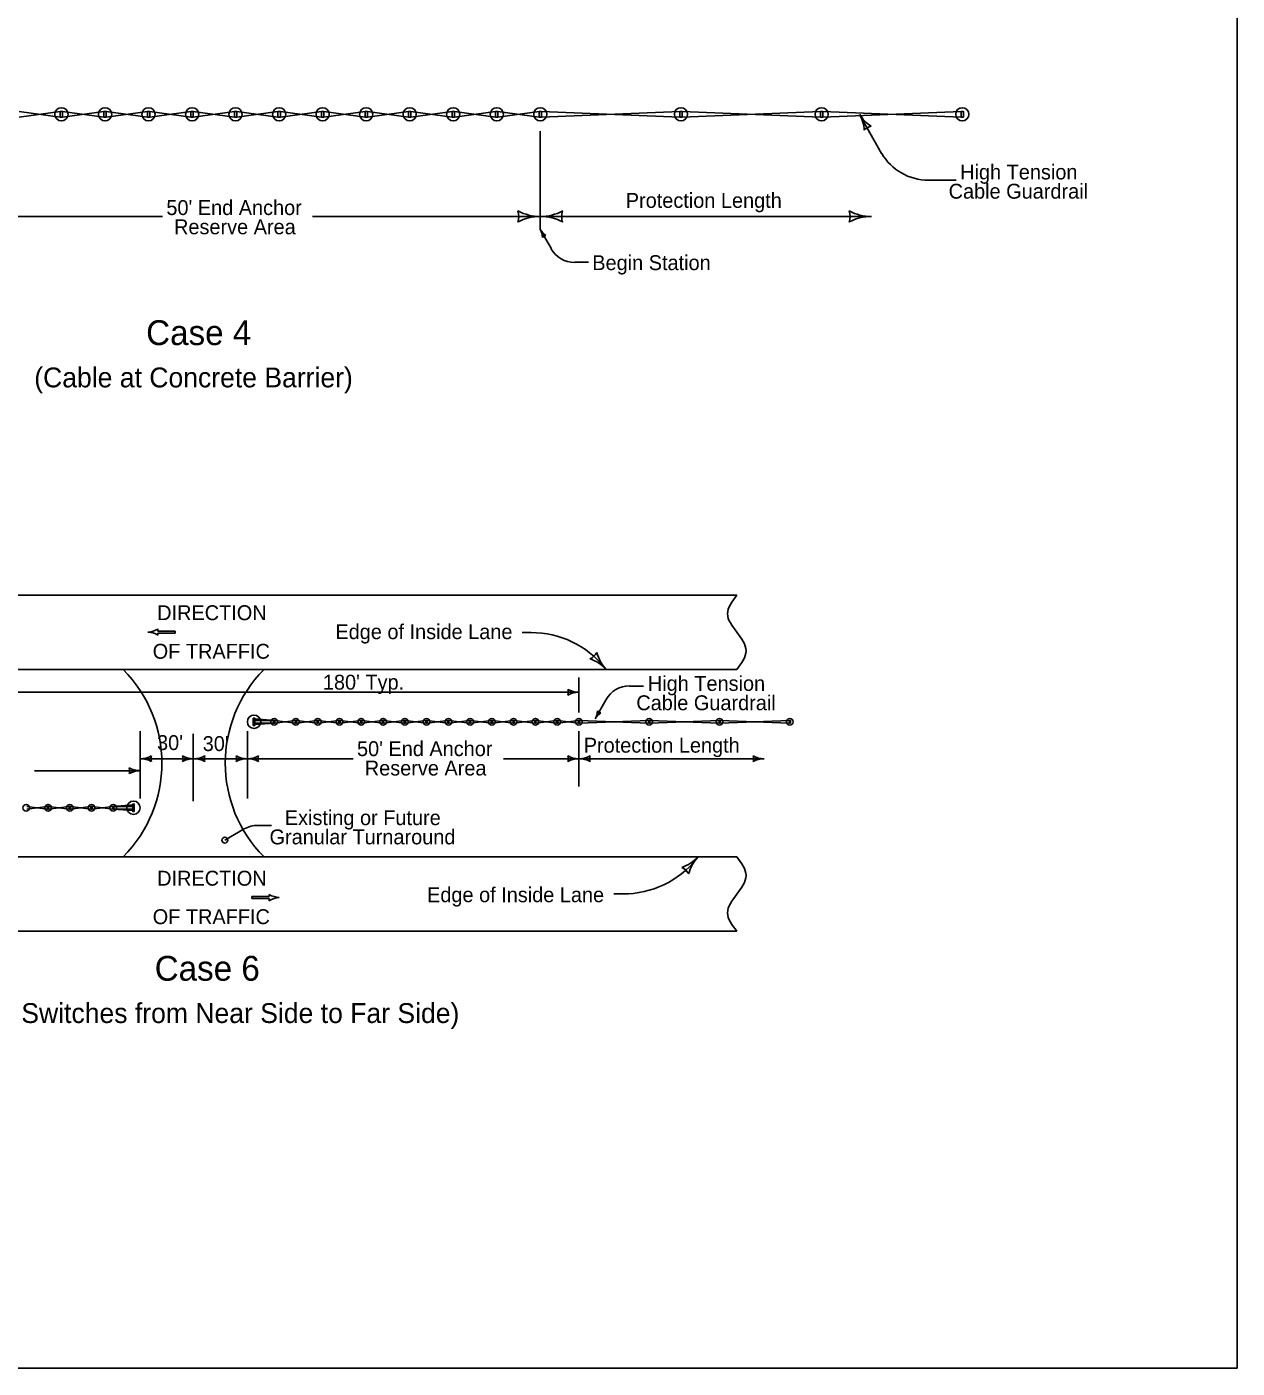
# Model space of a CAD drawing. Extents: x 10133 to 81668, y 7924 to 11018.
# Drawn here: x 23092 to 24068, y 7924 to 9005 of the extents above; entities that cross this region are included whole.
import ezdxf

# ---------------------------------------------------------------- set-up
doc = ezdxf.new("R2010")
doc.units = 0
for name, color, linetype in [('dsnCellElements', 7, 'Continuous'), ('DsnShtRevisedText', 7, 'Continuous'), ('dsnStdDimension', 7, 'Continuous'), ('Level 8', 7, 'Continuous'), ('SheetBorder', 7, 'Continuous')]:
    doc.layers.add(name, color=color, linetype=linetype)

msp = doc.modelspace()

# ---------------------------------------------------------------- linework, layer by layer
at = {"layer": 'dsnCellElements'}
for p, q in [((23085.5, 8936.9), (23118.7, 8932.4)), ((23085.5, 8932.4), (23118.7, 8936.9)), ((23120.6, 8936.9), (23153.8, 8932.4)), ((23120.6, 8932.4), (23153.8, 8936.9)), ((23155.7, 8936.9), (23188.9, 8932.4)), ((23155.7, 8932.4), (23188.9, 8936.9)), ((23190.8, 8936.9), (23224, 8932.4)), ((23190.8, 8932.4), (23224, 8936.9)), ((23225.9, 8932.4), (23259.1, 8936.9)), ((23225.9, 8936.9), (23259.1, 8932.4)), ((23261, 8936.9), (23294.2, 8932.4)), ((23261, 8932.4), (23294.2, 8936.9)), ((23296.1, 8936.9), (23329.3, 8932.4)), ((23296.1, 8932.4), (23329.3, 8936.9)), ((23331.1, 8936.9), (23364.4, 8932.4)), ((23331.1, 8932.4), (23364.4, 8936.9)), ((23366.3, 8936.9), (23399.4, 8932.4)), ((23366.3, 8932.4), (23399.4, 8936.9)), ((23401.3, 8936.9), (23434.6, 8932.4)), ((23401.3, 8932.4), (23434.6, 8936.9)), ((23436.5, 8936.9), (23469.6, 8932.4)), ((23436.5, 8932.4), (23469.6, 8936.9)), ((23471.5, 8936.9), (23504.8, 8932.4)), ((23471.5, 8932.4), (23504.8, 8936.9)), ((23506.6, 8936.9), (23618.2, 8932.4)), ((23506.6, 8932.4), (23618.2, 8936.9)), ((23620, 8936.9), (23731.6, 8932.4)), ((23620, 8932.4), (23731.6, 8936.9)), ((23733.4, 8936.9), (23845, 8932.4)), ((23733.4, 8932.4), (23845, 8936.9)), ((23274.9, 8447.3), (23291.6, 8446.1)), ((23274.9, 8446.1), (23290.7, 8446.1)), ((23274.9, 8443.9), (23290.7, 8443.9)), ((23274.9, 8442.7), (23291.6, 8443.9)), ((23291.6, 8443.9), (23308.2, 8446.1)), ((23291.6, 8446.1), (23308.2, 8443.9)), ((23309.2, 8443.9), (23325.8, 8446.1)), ((23309.2, 8446.1), (23325.8, 8443.9)), ((23326.7, 8443.9), (23343.3, 8446.1)), ((23326.7, 8446.1), (23343.3, 8443.9)), ((23344.3, 8443.9), (23360.9, 8446.1)), ((23344.3, 8446.1), (23360.9, 8443.9)), ((23361.8, 8443.9), (23378.4, 8446.1)), ((23361.8, 8446.1), (23378.4, 8443.9)), ((23379.4, 8443.9), (23396, 8446.1)), ((23379.4, 8446.1), (23396, 8443.9)), ((23396.9, 8446.1), (23413.5, 8443.9)), ((23396.9, 8443.9), (23413.5, 8446.1)), ((23414.5, 8443.9), (23431.1, 8446.1)), ((23414.5, 8446.1), (23431.1, 8443.9)), ((23432, 8443.9), (23448.6, 8446.1)), ((23432, 8446.1), (23448.6, 8443.9)), ((23449.5, 8443.9), (23466.2, 8446.1)), ((23449.5, 8446.1), (23466.2, 8443.9)), ((23467.1, 8443.9), (23483.7, 8446.1)), ((23467.1, 8446.1), (23483.7, 8443.9)), ((23484.6, 8443.9), (23501.3, 8446.1)), ((23484.6, 8446.1), (23501.3, 8443.9)), ((23502.2, 8443.9), (23518.8, 8446.1)), ((23502.2, 8446.1), (23518.8, 8443.9)), ((23519.7, 8443.9), (23536.4, 8446.1)), ((23519.7, 8446.1), (23536.4, 8443.9)), ((23537.3, 8443.9), (23593.1, 8446.1)), ((23537.3, 8446.1), (23593.1, 8443.9)), ((23594, 8443.9), (23649.8, 8446.1)), ((23594, 8446.1), (23649.8, 8443.9)), ((23650.7, 8443.9), (23706.5, 8446.1)), ((23650.7, 8446.1), (23706.5, 8443.9)), ((23108.3, 8376.8), (23091.7, 8374.6)), ((23108.3, 8374.6), (23091.7, 8376.8)), ((23125.9, 8376.8), (23109.3, 8374.6)), ((23125.9, 8374.6), (23109.3, 8376.8)), ((23143.4, 8376.8), (23126.8, 8374.6)), ((23143.4, 8374.6), (23126.8, 8376.8)), ((23161, 8376.8), (23144.4, 8374.6)), ((23161, 8374.6), (23144.4, 8376.8)), ((23177.7, 8378), (23161, 8376.8)), ((23177.7, 8373.4), (23161, 8374.6)), ((23177.7, 8376.8), (23161.9, 8376.8)), ((23177.7, 8374.6), (23161.9, 8374.6))]:
    msp.add_line(p, q, dxfattribs=at)
for points in [[(23118.7, 8932.4), (23118.7, 8936.9), (23120.6, 8936.9), (23120.6, 8932.4)], [(23153.9, 8932.4), (23153.9, 8936.9), (23155.7, 8936.9), (23155.7, 8932.4)], [(23188.9, 8932.4), (23188.9, 8936.9), (23190.8, 8936.9), (23190.8, 8932.4)], [(23224, 8932.4), (23224, 8936.9), (23225.9, 8936.9), (23225.9, 8932.4)], [(23259.1, 8932.4), (23259.1, 8936.9), (23261, 8936.9), (23261, 8932.4)], [(23294.2, 8932.4), (23294.2, 8936.9), (23296.1, 8936.9), (23296.1, 8932.4)], [(23329.3, 8932.4), (23329.3, 8936.9), (23331.1, 8936.9), (23331.1, 8932.4)], [(23364.4, 8932.4), (23364.4, 8936.9), (23366.3, 8936.9), (23366.3, 8932.4)], [(23399.4, 8932.4), (23399.4, 8936.9), (23401.3, 8936.9), (23401.3, 8932.4)], [(23434.6, 8932.4), (23434.6, 8936.9), (23436.5, 8936.9), (23436.5, 8932.4)], [(23469.6, 8932.4), (23469.6, 8936.9), (23471.5, 8936.9), (23471.5, 8932.4)], [(23504.8, 8932.4), (23504.8, 8936.9), (23506.6, 8936.9), (23506.6, 8932.4)], [(23504.8, 8932.4), (23504.8, 8936.9), (23506.6, 8936.9), (23506.6, 8932.4)], [(23618.2, 8932.4), (23618.2, 8936.9), (23620, 8936.9), (23620, 8932.4)], [(23618.2, 8932.4), (23618.2, 8936.9), (23620, 8936.9), (23620, 8932.4)], [(23731.6, 8932.4), (23731.6, 8936.9), (23733.4, 8936.9), (23733.4, 8932.4)], [(23731.6, 8932.4), (23731.6, 8936.9), (23733.4, 8936.9), (23733.4, 8932.4)], [(23845, 8932.4), (23845, 8936.9), (23846.8, 8936.9), (23846.8, 8932.4)], [(23274.3, 8448), (23274.3, 8442), (23275.5, 8442), (23275.5, 8448)], [(23290.7, 8446.1), (23290.7, 8443.9), (23291.6, 8443.9), (23291.6, 8446.1)], [(23308.2, 8446.1), (23308.2, 8443.9), (23309.2, 8443.9), (23309.2, 8446.1)], [(23325.8, 8446.1), (23325.8, 8443.9), (23326.7, 8443.9), (23326.7, 8446.1)], [(23343.3, 8446.1), (23343.3, 8443.9), (23344.3, 8443.9), (23344.3, 8446.1)], [(23360.9, 8446.1), (23360.9, 8443.9), (23361.8, 8443.9), (23361.8, 8446.1)], [(23378.4, 8446.1), (23378.4, 8443.9), (23379.4, 8443.9), (23379.4, 8446.1)], [(23396, 8446.1), (23396, 8443.9), (23396.9, 8443.9), (23396.9, 8446.1)], [(23413.5, 8446.1), (23413.5, 8443.9), (23414.5, 8443.9), (23414.5, 8446.1)], [(23431.1, 8446.1), (23431.1, 8443.9), (23432, 8443.9), (23432, 8446.1)], [(23448.6, 8446.1), (23448.6, 8443.9), (23449.5, 8443.9), (23449.5, 8446.1)], [(23466.2, 8446.1), (23466.2, 8443.9), (23467.1, 8443.9), (23467.1, 8446.1)], [(23483.7, 8446.1), (23483.7, 8443.9), (23484.6, 8443.9), (23484.6, 8446.1)], [(23501.3, 8446.1), (23501.3, 8443.9), (23502.2, 8443.9), (23502.2, 8446.1)], [(23518.8, 8446.1), (23518.8, 8443.9), (23519.7, 8443.9), (23519.7, 8446.1)], [(23536.4, 8446.1), (23536.4, 8443.9), (23537.3, 8443.9), (23537.3, 8446.1)], [(23536.4, 8446.1), (23536.4, 8443.9), (23537.3, 8443.9), (23537.3, 8446.1)], [(23593.1, 8446.1), (23593.1, 8443.9), (23594, 8443.9), (23594, 8446.1)], [(23593.1, 8446.1), (23593.1, 8443.9), (23594, 8443.9), (23594, 8446.1)], [(23649.8, 8446.1), (23649.8, 8443.9), (23650.7, 8443.9), (23650.7, 8446.1)], [(23649.8, 8446.1), (23649.8, 8443.9), (23650.7, 8443.9), (23650.7, 8446.1)], [(23706.5, 8446.1), (23706.5, 8443.9), (23707.4, 8443.9), (23707.4, 8446.1)], [(23178.3, 8372.7), (23178.3, 8378.7), (23177.1, 8378.7), (23177.1, 8372.7)], [(23109.3, 8374.6), (23109.3, 8376.8), (23108.3, 8376.8), (23108.3, 8374.6)], [(23126.8, 8374.6), (23126.8, 8376.8), (23125.9, 8376.8), (23125.9, 8374.6)], [(23144.4, 8374.6), (23144.4, 8376.8), (23143.4, 8376.8), (23143.4, 8374.6)], [(23161.9, 8374.6), (23161.9, 8376.8), (23161, 8376.8), (23161, 8374.6)]]:
    msp.add_lwpolyline(points, close=True, dxfattribs=at)
for centre, radius in [((23119.6, 8934.6), 5.32), ((23154.8, 8934.6), 5.32), ((23189.8, 8934.6), 5.32), ((23225, 8934.6), 5.32), ((23260, 8934.6), 5.32), ((23295.2, 8934.6), 5.32), ((23330.2, 8934.6), 5.32), ((23365.3, 8934.6), 5.32), ((23400.4, 8934.6), 5.32), ((23435.5, 8934.6), 5.32), ((23470.6, 8934.6), 5.32), ((23505.7, 8934.6), 5.32), ((23505.7, 8934.6), 5.32), ((23619.1, 8934.6), 5.32), ((23619.1, 8934.6), 5.32), ((23732.5, 8934.6), 5.32), ((23732.5, 8934.6), 5.32), ((23845.9, 8934.6), 5.32), ((23274.9, 8445), 5.4), ((23291.2, 8445), 2.66), ((23308.7, 8445), 2.66), ((23326.3, 8445), 2.66), ((23343.8, 8445), 2.66), ((23361.4, 8445), 2.66), ((23378.9, 8445), 2.66), ((23396.5, 8445), 2.66), ((23414, 8445), 2.66), ((23431.6, 8445), 2.66), ((23449.1, 8445), 2.66), ((23466.6, 8445), 2.66), ((23484.2, 8445), 2.66), ((23501.7, 8445), 2.66), ((23519.3, 8445), 2.66), ((23536.8, 8445), 2.66), ((23536.8, 8445), 2.66), ((23593.5, 8445), 2.66), ((23593.5, 8445), 2.66), ((23650.2, 8445), 2.66), ((23650.2, 8445), 2.66), ((23706.9, 8445), 2.66), ((23091.2, 8375.7), 2.66), ((23108.8, 8375.7), 2.66), ((23126.3, 8375.7), 2.66), ((23143.9, 8375.7), 2.66), ((23161.4, 8375.7), 2.66), ((23177.7, 8375.7), 5.4)]:
    msp.add_circle(centre, radius, dxfattribs=at)
at = {"layer": 'DsnShtRevisedText'}
for p, q in [((23780.9, 8903.1), (23763.1, 8934.4)), ((23505.7, 8841.7), (23505.7, 8921)), ((23818.5, 8881.5), (23841, 8881.5)), ((22971, 8852.2), (23201.1, 8852.2)), ((23322.1, 8852.2), (23548.6, 8852.2)), ((23548.6, 8852.2), (23716.6, 8852.2)), ((23716.6, 8852.2), (23772.8, 8852.2)), ((23514.6, 8826.1), (23505.7, 8841.7)), ((23533.4, 8815.3), (23544.6, 8815.3)), ((23197.3, 8519.8), (23197.3, 8518)), ((23189.2, 8517.2), (23189.2, 8517.2)), ((23197.3, 8518), (23211.3, 8518)), ((23211.3, 8516.5), (23197.3, 8516.5)), ((23197.3, 8516.5), (23197.3, 8514.7)), ((23211.3, 8518), (23211.3, 8516.5)), ((23491, 8516.9), (23498.4, 8516.9)), ((23536.8, 8452.5), (23536.8, 8480.8)), ((23207.3, 8468.8), (22915.8, 8468.8)), ((23536.8, 8468.8), (23207.3, 8468.8)), ((23577.5, 8473.8), (23588.8, 8473.8)), ((23558.7, 8463), (23549.8, 8447.4)), ((23183.1, 8383.2), (23183.1, 8437.5)), ((23225.7, 8381), (23225.7, 8435.2)), ((23269.5, 8437.5), (23269.5, 8383.2)), ((23536.8, 8437.5), (23536.8, 8392.9)), ((23269.5, 8415.2), (23183.1, 8415.2)), ((23269.5, 8415.2), (23354.9, 8415.2)), ((23475.9, 8415.2), (23536.8, 8415.2)), ((23536.8, 8415.2), (23559.1, 8415.2)), ((23559.1, 8415.2), (23686.2, 8415.2)), ((23183.1, 8405.5), (23098, 8405.5)), ((23267, 8358.6), (23251.4, 8349.6)), ((23277.8, 8361.5), (23289.1, 8361.5)), ((23287.2, 8304.1), (23273.2, 8304.1)), ((23273.2, 8304.1), (23273.2, 8302.5)), ((23287.2, 8305.8), (23287.2, 8304.1)), ((23295.3, 8303.3), (23295.3, 8303.3)), ((23564.9, 8306.3), (23572.4, 8306.3)), ((23273.2, 8302.5), (23287.2, 8302.5)), ((23287.2, 8302.5), (23287.2, 8300.8))]:
    msp.add_line(p, q, dxfattribs=at)
msp.add_circle((23251.4, 8349.6), 2.4, dxfattribs=at)
for centre, radius, start, end in [((23739.6, 8920.7), 27.2, 2.1589, 30.2314), ((23786.7, 8948.1), 27.2, 210.2314, 238.3038), ((23774.6, 8914.7), 10.5, 102.498, 137.9647), ((23818.5, 8925), 43.5, 210.2243, 270), ((23473.6, 8852.2), 14.8, 342.2666, 17.7333), ((23505.7, 8890.5), 38.3, 241.9275, 270), ((23505.7, 8890.5), 38.3, 270, 298.0725), ((23537.8, 8852.2), 14.8, 162.2666, 197.7334), ((23740.7, 8852.2), 14.8, 342.2666, 17.7333), ((23772.7, 8890.5), 38.3, 241.9275, 270), ((23505.7, 8814), 38.3, 90, 118.0725), ((23505.7, 8814), 38.3, 61.9275, 90), ((23772.7, 8814), 38.3, 90, 118.0725), ((23493.9, 8834.9), 13.6, 2.1589, 30.2314), ((23517.4, 8848.6), 13.6, 210.2314, 238.3038), ((23511.4, 8831.9), 5.25, 102.498, 137.9647), ((23533.4, 8837), 21.8, 210.2243, 270), ((23188.6, 8533.6), 16.4, 272.352, 302.382), ((23188.6, 8500.9), 16.4, 57.618, 87.648), ((23498.4, 8440.7), 76.2, 39.0106, 90), ((23540.4, 8506.9), 12.5, 295.2639, 330.7306), ((23582.6, 8509.1), 32.4, 194.9248, 222.9973), ((23093.9, 8411.6), 106.7, 315, 45), ((23358.4, 8411.6), 106.7, 135, 225), ((23535.3, 8465), 32.4, 42.9973, 71.0698), ((23520.8, 8468.8), 7.39, 342.2666, 17.7333), ((23536.8, 8487.9), 19.1, 241.9275, 270), ((23536.8, 8449.7), 19.1, 90, 118.0725), ((23577.5, 8452.1), 21.8, 90, 149.7757), ((23538.1, 8454.2), 13.6, 329.7686, 357.8411), ((23561.6, 8440.5), 13.6, 121.6962, 149.7686), ((23555.6, 8457.2), 5.25, 222.0353, 257.502), ((23183.1, 8434.3), 19.1, 270, 298.0725), ((23183.1, 8396.1), 19.1, 61.9275, 90), ((23199.2, 8415.2), 7.39, 162.2666, 197.7334), ((23210.3, 8415.2), 7.39, 342.2666, 17.7333), ((23226.3, 8434.3), 19.1, 241.9275, 270), ((23226.3, 8396.1), 19.1, 90, 118.0725), ((23226.3, 8434.3), 19.1, 270, 298.0725), ((23226.3, 8396.1), 19.1, 61.9275, 90), ((23242.3, 8415.2), 7.39, 162.2666, 197.7334), ((23253.4, 8415.2), 7.39, 342.2666, 17.7333), ((23269.5, 8434.3), 19.1, 241.9275, 270), ((23269.5, 8396.1), 19.1, 90, 118.0725), ((23269.5, 8434.3), 19.1, 270, 298.0725), ((23269.5, 8396.1), 19.1, 61.9275, 90), ((23285.5, 8415.2), 7.39, 162.2666, 197.7334), ((23520.8, 8415.2), 7.39, 342.2667, 17.7334), ((23536.8, 8434.3), 19.1, 241.9275, 270), ((23536.8, 8396.1), 19.1, 90, 118.0725), ((23536.8, 8434.3), 19.1, 270, 298.0725), ((23536.8, 8396.1), 19.1, 61.9275, 90), ((23552.9, 8415.2), 7.39, 162.2666, 197.7334), ((23670.2, 8415.2), 7.39, 342.2667, 17.7334), ((23686.2, 8434.3), 19.1, 241.9275, 270), ((23686.2, 8396.1), 19.1, 90, 118.0725), ((23167.1, 8405.5), 7.39, 342.2666, 17.7333), ((23183.1, 8424.7), 19.1, 241.9275, 270), ((23183.1, 8386.4), 19.1, 90, 118.0725), ((23277.7, 8339.7), 21.8, 89.6565, 119.5443), ((23609.2, 8358.2), 32.4, 288.9302, 317.0027), ((23656.6, 8314), 32.4, 137.0027, 165.0752), ((23572.4, 8382.4), 76.2, 270, 320.9894), ((23614.4, 8316.3), 12.5, 29.2694, 64.7361), ((23295.9, 8319.7), 16.4, 237.618, 267.648), ((23295.9, 8286.9), 16.4, 92.352, 122.382)]:
    msp.add_arc(centre, radius, start, end, dxfattribs=at)
at = {"layer": 'dsnStdDimension'}
for p, q in [((22788.5, 8547.1), (23664.1, 8547.1)), ((22788.5, 8487.1), (23664.1, 8487.1)), ((22788.5, 8336.1), (23664.1, 8336.1)), ((22788.5, 8276.1), (23664.1, 8276.1))]:
    msp.add_line(p, q, dxfattribs=at)
for points in [[(23664.1, 8487.1), (23671.6, 8502.1), (23664.1, 8517.1), (23656.6, 8532.1), (23664.1, 8547.1)], [(23664.1, 8336.1), (23671.6, 8321.1), (23664.1, 8306.1), (23656.6, 8291.1), (23664.1, 8276.1)]]:
    msp.add_spline(points, degree=3, dxfattribs=at)
at = {"layer": 'SheetBorder'}
msp.add_lwpolyline([(20932.5, 9944), (24067.5, 9944), (24067.5, 7924), (20932.5, 7924)], close=True, dxfattribs=at)

# ---------------------------------------------------------------- texts
at = {"layer": 'DsnShtRevisedText'}
for s, p in [('High Tension', (23844.2, 8882.1)), ('Cable Guardrail', (23834.9, 8866.6)), ("50' End Anchor", (23204.2, 8853.4)), ('Protection Length', (23574.6, 8859.2)), ('Reserve Area', (23210.4, 8837.9)), ('Begin Station', (23547.6, 8809)), ('DIRECTION', (23196.8, 8526.9)), ('Edge of Inside Lane', (23340.5, 8511.6)), ('OF TRAFFIC', (23193.2, 8495.8)), ("180' Typ.", (23330.4, 8470.9)), ('High Tension', (23592.4, 8469.9)), ('Cable Guardrail', (23583.1, 8454.3)), ("30'", (23196.7, 8422.2)), ("30'", (23233.5, 8421.4)), ('Protection Length', (23540.7, 8420.1)), ("50' End Anchor", (23357.9, 8417.3)), ('Reserve Area', (23364.2, 8401.7)), ('Existing or Future', (23299.7, 8361.7)), ('Granular Turnaround', (23287.4, 8346.2)), ('DIRECTION', (23196.8, 8312.9)), ('Edge of Inside Lane', (23414.4, 8299.6)), ('OF TRAFFIC', (23193.2, 8281.9))]:
    msp.add_text(s, height=12, dxfattribs=at).set_placement(p)
at = {"layer": 'Level 8'}
for s, height, p in [('Case 4', 20, (23187.9, 8748.6)), ('(Cable at Concrete Barrier)', 16, (23097.7, 8714.5)), ('Case 6', 20, (23194.8, 8236.3)), ('(Cable Switches from Near Side to Far Side)', 16, (23018.3, 8202.2))]:
    msp.add_text(s, height=height, dxfattribs=at).set_placement(p)

doc.saveas('drawing.dxf')
